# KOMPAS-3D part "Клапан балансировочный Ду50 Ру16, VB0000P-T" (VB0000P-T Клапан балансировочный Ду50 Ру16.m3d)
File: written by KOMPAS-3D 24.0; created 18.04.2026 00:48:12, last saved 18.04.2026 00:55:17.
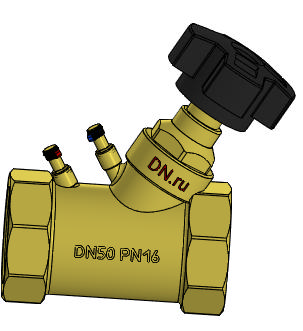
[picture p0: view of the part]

Document properties: Автор: tyuri; Полное имя файла: E:\Работа\Зайцев\АУТСОРС\Диман\Балансировка\VB0000P-T Клапан балансировочный DN.ru Ду15-50 Ру16\DN50\VB0000P-T Клапан балансировочный Ду50 Ру16.m3d

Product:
- Body: Тело 2  | qty 1
    Масса: 2.729662
- Part/product: Клапан балансировочный Ду50 Ру16  | designation VB0000P-T
    Масса: 1.47
    Раздел спецификации: Прочие изделия
    Примечание: D080-01096

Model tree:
1. Операция без истории:1

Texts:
  VB0000P-T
